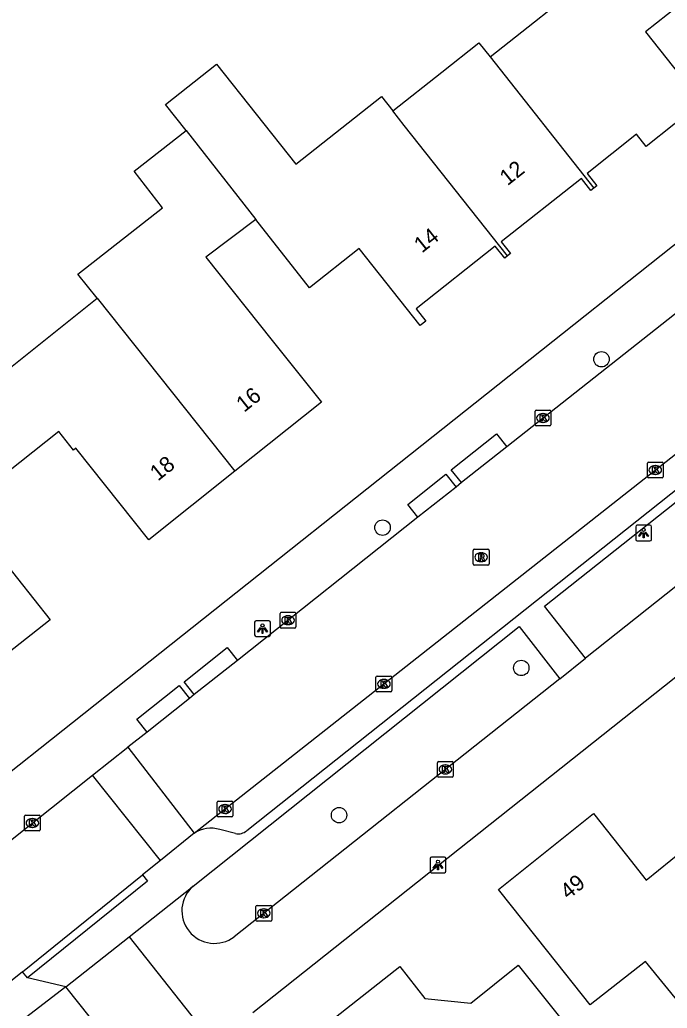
# Model space of a CAD drawing. Extents: x 159503 to 160347, y 382525 to 383272.
# Drawn here: x 159954.6 to 159995.6, y 383112.7 to 383175.2 of the extents above; entities that cross this region are included whole.
import ezdxf

# ---------------------------------------------------------------- set-up
doc = ezdxf.new("R2010")
doc.units = 0
for name, color, linetype in [('IMGEO_Boom', 7, 'Continuous'), ('IMGEO_Kolk', 7, 'Continuous'), ('IMGEO_Lichtpunt', 7, 'Continuous'), ('IMGEO_Pand', 7, 'Continuous'), ('IMGEO_Pand_nummerreeks', 7, 'Continuous'), ('IMGEO_Rijbaan_lokaal_open', 7, 'Continuous'), ('IMGEO_Rioolput', 7, 'Continuous'), ('IMGEO_Voetpad_open', 7, 'Continuous')]:
    doc.layers.add(name, color=color, linetype=linetype)

msp = doc.modelspace()

# ---------------------------------------------------------------- linework, layer by layer
at = {"layer": 'IMGEO_Boom'}
for centre in [(159991.403, 383153.748), (159977.549, 383143.088), (159986.328, 383134.208), (159974.796, 383124.886)]:
    msp.add_circle(centre, 0.489, dxfattribs=at)
at = {"layer": 'IMGEO_Kolk'}
for p, q in [((159987.201, 383149.604), (159987.201, 383150.456)), ((159987.276, 383150.53), (159988.128, 383150.53)), ((159987.689, 383150.31), (159987.714, 383150.31)), ((159988.202, 383150.456), (159988.202, 383149.604)), ((159988.128, 383149.53), (159987.276, 383149.53)), ((159987.712, 383149.75), (159987.687, 383149.75)), ((159994.308, 383146.308), (159994.308, 383147.16)), ((159994.383, 383147.234), (159995.235, 383147.234)), ((159994.796, 383147.014), (159994.821, 383147.014)), ((159995.309, 383147.16), (159995.309, 383146.308)), ((159994.819, 383146.454), (159994.794, 383146.454)), ((159995.235, 383146.234), (159994.383, 383146.234)), ((159971.064, 383136.801), (159971.064, 383137.653)), ((159971.139, 383137.727), (159971.991, 383137.727)), ((159972.065, 383137.653), (159972.065, 383136.801)), ((159971.552, 383137.507), (159971.577, 383137.507)), ((159971.991, 383136.727), (159971.139, 383136.727)), ((159971.575, 383136.947), (159971.55, 383136.947)), ((159977.131, 383132.77), (159977.131, 383133.622)), ((159977.206, 383133.696), (159978.058, 383133.696)), ((159977.619, 383133.476), (159977.644, 383133.476)), ((159978.132, 383133.622), (159978.132, 383132.77)), ((159978.058, 383132.696), (159977.206, 383132.696)), ((159977.642, 383132.916), (159977.617, 383132.916)), ((159981.097, 383128.283), (159981.949, 383128.283)), ((159981.022, 383127.357), (159981.022, 383128.209)), ((159981.51, 383128.063), (159981.535, 383128.063)), ((159982.023, 383128.209), (159982.023, 383127.357)), ((159981.949, 383127.283), (159981.097, 383127.283)), ((159981.533, 383127.503), (159981.508, 383127.503)), ((159967.153, 383125.773), (159968.005, 383125.773)), ((159967.078, 383124.847), (159967.078, 383125.699)), ((159967.566, 383125.553), (159967.591, 383125.553)), ((159968.079, 383125.699), (159968.079, 383124.847)), ((159954.884, 383123.961), (159954.884, 383124.813)), ((159954.959, 383124.887), (159955.811, 383124.887)), ((159955.372, 383124.667), (159955.397, 383124.667)), ((159955.885, 383124.813), (159955.885, 383123.961)), ((159968.005, 383124.773), (159967.153, 383124.773)), ((159967.589, 383124.993), (159967.564, 383124.993)), ((159955.811, 383123.887), (159954.959, 383123.887)), ((159955.395, 383124.107), (159955.37, 383124.107)), ((159969.532, 383118.248), (159969.532, 383119.1)), ((159969.607, 383119.174), (159970.459, 383119.174)), ((159970.02, 383118.954), (159970.045, 383118.954)), ((159970.533, 383119.1), (159970.533, 383118.248)), ((159970.043, 383118.394), (159970.018, 383118.394)), ((159970.459, 383118.174), (159969.607, 383118.174))]:
    msp.add_line(p, q, dxfattribs=at)
for points in [[(159987.201, 383149.604), (159987.201, 383150.456)], [(159987.276, 383150.53), (159988.128, 383150.53)], [(159987.522, 383150.23), (159987.645, 383150.23), (159987.645, 383150.079), (159987.775, 383150.23), (159987.939, 383150.23), (159987.793, 383150.079), (159987.946, 383149.83), (159987.794, 383149.83), (159987.709, 383149.994), (159987.645, 383149.927), (159987.645, 383149.83), (159987.522, 383149.83), (159987.522, 383150.23)], [(159988.202, 383150.456), (159988.202, 383149.604)], [(159988.128, 383149.53), (159987.276, 383149.53)], [(159994.308, 383146.308), (159994.308, 383147.16)], [(159994.383, 383147.234), (159995.235, 383147.234)], [(159995.309, 383147.16), (159995.309, 383146.308)], [(159994.629, 383146.934), (159994.752, 383146.934), (159994.752, 383146.783), (159994.882, 383146.934), (159995.046, 383146.934), (159994.9, 383146.783), (159995.053, 383146.534), (159994.901, 383146.534), (159994.816, 383146.698), (159994.752, 383146.631), (159994.752, 383146.534), (159994.629, 383146.534), (159994.629, 383146.934)], [(159995.235, 383146.234), (159994.383, 383146.234)], [(159971.064, 383136.801), (159971.064, 383137.653)], [(159971.139, 383137.727), (159971.991, 383137.727)], [(159972.065, 383137.653), (159972.065, 383136.801)], [(159971.385, 383137.427), (159971.508, 383137.427), (159971.508, 383137.276), (159971.638, 383137.427), (159971.802, 383137.427), (159971.656, 383137.276), (159971.809, 383137.027), (159971.657, 383137.027), (159971.572, 383137.191), (159971.508, 383137.124), (159971.508, 383137.027), (159971.385, 383137.027), (159971.385, 383137.427)], [(159971.991, 383136.727), (159971.139, 383136.727)], [(159977.131, 383132.77), (159977.131, 383133.622)], [(159977.206, 383133.696), (159978.058, 383133.696)], [(159977.452, 383133.396), (159977.575, 383133.396), (159977.575, 383133.245), (159977.705, 383133.396), (159977.869, 383133.396), (159977.723, 383133.245), (159977.876, 383132.996), (159977.724, 383132.996), (159977.639, 383133.16), (159977.575, 383133.093), (159977.575, 383132.996), (159977.452, 383132.996), (159977.452, 383133.396)], [(159978.132, 383133.622), (159978.132, 383132.77)], [(159978.058, 383132.696), (159977.206, 383132.696)], [(159981.097, 383128.283), (159981.949, 383128.283)], [(159981.022, 383127.357), (159981.022, 383128.209)], [(159981.343, 383127.983), (159981.466, 383127.983), (159981.466, 383127.832), (159981.596, 383127.983), (159981.76, 383127.983), (159981.614, 383127.832), (159981.767, 383127.583), (159981.615, 383127.583), (159981.53, 383127.747), (159981.466, 383127.68), (159981.466, 383127.583), (159981.343, 383127.583), (159981.343, 383127.983)], [(159982.023, 383128.209), (159982.023, 383127.357)], [(159981.949, 383127.283), (159981.097, 383127.283)], [(159967.153, 383125.773), (159968.005, 383125.773)], [(159967.078, 383124.847), (159967.078, 383125.699)], [(159967.399, 383125.473), (159967.522, 383125.473), (159967.522, 383125.322), (159967.652, 383125.473), (159967.816, 383125.473), (159967.67, 383125.322), (159967.823, 383125.073), (159967.671, 383125.073), (159967.586, 383125.237), (159967.522, 383125.17), (159967.522, 383125.073), (159967.399, 383125.073), (159967.399, 383125.473)], [(159968.079, 383125.699), (159968.079, 383124.847)], [(159954.884, 383123.961), (159954.884, 383124.813)], [(159954.959, 383124.887), (159955.811, 383124.887)], [(159955.205, 383124.587), (159955.328, 383124.587), (159955.328, 383124.436), (159955.458, 383124.587), (159955.622, 383124.587), (159955.476, 383124.436), (159955.629, 383124.187), (159955.477, 383124.187), (159955.392, 383124.351), (159955.328, 383124.284), (159955.328, 383124.187), (159955.205, 383124.187), (159955.205, 383124.587)], [(159955.885, 383124.813), (159955.885, 383123.961)], [(159968.005, 383124.773), (159967.153, 383124.773)], [(159955.811, 383123.887), (159954.959, 383123.887)], [(159969.532, 383118.248), (159969.532, 383119.1)], [(159969.607, 383119.174), (159970.459, 383119.174)], [(159969.853, 383118.874), (159969.976, 383118.874), (159969.976, 383118.723), (159970.106, 383118.874), (159970.27, 383118.874), (159970.124, 383118.723), (159970.277, 383118.474), (159970.125, 383118.474), (159970.04, 383118.638), (159969.976, 383118.571), (159969.976, 383118.474), (159969.853, 383118.474), (159969.853, 383118.874)], [(159970.533, 383119.1), (159970.533, 383118.248)], [(159970.459, 383118.174), (159969.607, 383118.174)]]:
    msp.add_lwpolyline(points, dxfattribs=at)
for centre, start, end in [((159987.278, 383150.454), 91.55205, 178.44795), ((159987.278, 383150.454), 91.55205, 178.44795), ((159988.126, 383150.454), 1.55205, 88.44795), ((159988.126, 383150.454), 1.55205, 88.44795), ((159987.278, 383149.606), 181.55205, 268.44795), ((159987.278, 383149.606), 181.55205, 268.44795), ((159988.126, 383149.606), 271.55205, 358.44795), ((159988.126, 383149.606), 271.55205, 358.44795), ((159994.385, 383147.158), 91.55205, 178.44795), ((159994.385, 383147.158), 91.55205, 178.44795), ((159995.233, 383147.158), 1.55205, 88.44795), ((159995.233, 383147.158), 1.55205, 88.44795), ((159994.385, 383146.31), 181.55205, 268.44795), ((159994.385, 383146.31), 181.55205, 268.44795), ((159995.233, 383146.31), 271.55205, 358.44795), ((159995.233, 383146.31), 271.55205, 358.44795), ((159971.141, 383137.651), 91.55205, 178.44795), ((159971.141, 383137.651), 91.55205, 178.44795), ((159971.989, 383137.651), 1.55205, 88.44795), ((159971.989, 383137.651), 1.55205, 88.44795), ((159971.141, 383136.803), 181.55205, 268.44795), ((159971.141, 383136.803), 181.55205, 268.44795), ((159971.989, 383136.803), 271.55205, 358.44795), ((159971.989, 383136.803), 271.55205, 358.44795), ((159977.208, 383133.62), 91.55205, 178.44795), ((159977.208, 383133.62), 91.55205, 178.44795), ((159978.056, 383133.62), 1.55205, 88.44795), ((159978.056, 383133.62), 1.55205, 88.44795), ((159977.208, 383132.772), 181.55205, 268.44795), ((159977.208, 383132.772), 181.55205, 268.44795), ((159978.056, 383132.772), 271.55205, 358.44795), ((159978.056, 383132.772), 271.55205, 358.44795), ((159981.099, 383128.207), 91.55205, 178.44795), ((159981.099, 383128.207), 91.55205, 178.44795), ((159981.947, 383128.207), 1.55205, 88.44795), ((159981.947, 383128.207), 1.55205, 88.44795), ((159981.099, 383127.359), 181.55205, 268.44795), ((159981.099, 383127.359), 181.55205, 268.44795), ((159981.947, 383127.359), 271.55205, 358.44795), ((159981.947, 383127.359), 271.55205, 358.44795), ((159967.155, 383125.697), 91.55205, 178.44795), ((159967.155, 383125.697), 91.55205, 178.44795), ((159968.003, 383125.697), 1.55205, 88.44795), ((159968.003, 383125.697), 1.55205, 88.44795), ((159954.961, 383124.811), 91.55205, 178.44795), ((159954.961, 383124.811), 91.55205, 178.44795), ((159955.809, 383124.811), 1.55205, 88.44795), ((159955.809, 383124.811), 1.55205, 88.44795), ((159967.155, 383124.849), 181.55205, 268.44795), ((159967.155, 383124.849), 181.55205, 268.44795), ((159968.003, 383124.849), 271.55205, 358.44795), ((159968.003, 383124.849), 271.55205, 358.44795), ((159954.961, 383123.963), 181.55205, 268.44795), ((159954.961, 383123.963), 181.55205, 268.44795), ((159955.809, 383123.963), 271.55205, 358.44795), ((159955.809, 383123.963), 271.55205, 358.44795), ((159969.609, 383119.098), 91.55205, 178.44795), ((159969.609, 383119.098), 91.55205, 178.44795), ((159970.457, 383119.098), 1.55205, 88.44795), ((159970.457, 383119.098), 1.55205, 88.44795), ((159969.609, 383118.25), 181.55205, 268.44795), ((159969.609, 383118.25), 181.55205, 268.44795), ((159970.457, 383118.25), 271.55205, 358.44795), ((159970.457, 383118.25), 271.55205, 358.44795)]:
    msp.add_arc(centre, 0.0765, start, end, dxfattribs=at)
for centre, major_axis, ratio, start_param, end_param in [((159987.688, 383150.03), (-0.387, 0.002), 0.722429, 4.712389, 7.853982), ((159987.713, 383150.03), (-0.39, 0.002), 0.717154, 1.570796, 4.712389), ((159994.795, 383146.734), (-0.387, 0.002), 0.722429, 4.712389, 7.853982), ((159994.82, 383146.734), (-0.39, 0.002), 0.717154, 1.570796, 4.712389), ((159971.551, 383137.227), (-0.387, 0.002), 0.722429, 4.712389, 7.853982), ((159971.576, 383137.227), (-0.39, 0.002), 0.717154, 1.570796, 4.712389), ((159977.618, 383133.196), (-0.387, 0.002), 0.722429, 4.712389, 7.853982), ((159977.643, 383133.196), (-0.39, 0.002), 0.717154, 1.570796, 4.712389), ((159981.509, 383127.783), (-0.387, 0.002), 0.722429, 4.712389, 7.853982), ((159981.534, 383127.783), (-0.39, 0.002), 0.717154, 1.570796, 4.712389), ((159967.565, 383125.273), (-0.387, 0.002), 0.722429, 4.712389, 7.853982), ((159967.59, 383125.273), (-0.39, 0.002), 0.717154, 1.570796, 4.712389), ((159955.371, 383124.387), (-0.387, 0.002), 0.722429, 4.712389, 7.853982), ((159955.396, 383124.387), (-0.39, 0.002), 0.717154, 1.570796, 4.712389), ((159970.019, 383118.674), (-0.387, 0.002), 0.722429, 4.712389, 7.853982), ((159970.044, 383118.674), (-0.39, 0.002), 0.717154, 1.570796, 4.712389)]:
    msp.add_ellipse(centre, major_axis=major_axis, ratio=ratio, start_param=start_param, end_param=end_param, dxfattribs=at)
at = {"layer": 'IMGEO_Lichtpunt'}
for p, q in [((159993.573, 383143.149), (159993.573, 383142.342)), ((159993.573, 383143.149), (159993.573, 383142.342)), ((159994.475, 383143.244), (159993.667, 383143.244)), ((159994.475, 383143.244), (159993.667, 383143.244)), ((159994.569, 383142.342), (159994.569, 383143.149)), ((159994.569, 383142.342), (159994.569, 383143.149)), ((159993.667, 383142.248), (159994.475, 383142.248)), ((159993.667, 383142.248), (159994.475, 383142.248)), ((159969.452, 383137.103), (159969.452, 383136.296)), ((159969.452, 383137.103), (159969.452, 383136.296)), ((159970.354, 383137.198), (159969.546, 383137.198)), ((159970.354, 383137.198), (159969.546, 383137.198)), ((159970.448, 383136.296), (159970.448, 383137.103)), ((159970.448, 383136.296), (159970.448, 383137.103)), ((159969.546, 383136.202), (159970.354, 383136.202)), ((159969.546, 383136.202), (159970.354, 383136.202)), ((159980.557, 383122.142), (159980.557, 383121.335)), ((159980.557, 383122.142), (159980.557, 383121.335)), ((159981.459, 383122.237), (159980.651, 383122.237)), ((159981.459, 383122.237), (159980.651, 383122.237)), ((159981.553, 383121.335), (159981.553, 383122.142)), ((159981.553, 383121.335), (159981.553, 383122.142)), ((159980.651, 383121.241), (159981.459, 383121.241)), ((159980.651, 383121.241), (159981.459, 383121.241))]:
    msp.add_line(p, q, dxfattribs=at)
for points in [[(159993.947, 383142.813), (159993.986, 383142.785), (159993.798, 383142.523), (159993.76, 383142.55), (159993.947, 383142.813)], [(159994.049, 383142.765), (159994.096, 383142.765), (159994.096, 383142.443), (159994.049, 383142.443), (159994.049, 383142.765)], [(159994.159, 383142.785), (159994.197, 383142.812), (159994.384, 383142.55), (159994.345, 383142.522), (159994.159, 383142.785)], [(159969.826, 383136.767), (159969.865, 383136.739), (159969.677, 383136.477), (159969.639, 383136.504), (159969.826, 383136.767)], [(159969.928, 383136.719), (159969.975, 383136.719), (159969.975, 383136.397), (159969.928, 383136.397), (159969.928, 383136.719)], [(159970.038, 383136.739), (159970.076, 383136.766), (159970.263, 383136.504), (159970.224, 383136.476), (159970.038, 383136.739)], [(159980.931, 383121.806), (159980.97, 383121.778), (159980.782, 383121.516), (159980.744, 383121.543), (159980.931, 383121.806)], [(159981.033, 383121.758), (159981.08, 383121.758), (159981.08, 383121.436), (159981.033, 383121.436), (159981.033, 383121.758)], [(159981.143, 383121.778), (159981.181, 383121.805), (159981.368, 383121.543), (159981.329, 383121.515), (159981.143, 383121.778)]]:
    msp.add_lwpolyline(points, dxfattribs=at)
for centre in [(159994.072, 383142.947), (159969.951, 383136.901), (159981.056, 383121.94)]:
    msp.add_circle(centre, 0.0994, dxfattribs=at)
for centre, start, end in [((159993.667, 383143.149), 90, 180), ((159993.667, 383143.149), 90, 180), ((159994.475, 383143.149), 0, 90), ((159994.475, 383143.149), 0, 90), ((159993.667, 383142.342), 180, 270), ((159993.667, 383142.342), 180, 270), ((159994.475, 383142.342), 270, 0), ((159994.475, 383142.342), 270, 360), ((159969.546, 383137.103), 90, 180), ((159969.546, 383137.103), 90, 180), ((159970.354, 383137.103), 0, 90), ((159970.354, 383137.103), 0, 90), ((159969.546, 383136.296), 180, 270), ((159969.546, 383136.296), 180, 270), ((159970.354, 383136.296), 270, 0), ((159970.354, 383136.296), 270, 360), ((159980.651, 383122.142), 90, 180), ((159980.651, 383122.142), 90, 180), ((159981.459, 383122.142), 0, 90), ((159981.459, 383122.142), 0, 90), ((159980.651, 383121.335), 180, 270), ((159980.651, 383121.335), 180, 270), ((159981.459, 383121.335), 270, 0), ((159981.459, 383121.335), 270, 360)]:
    msp.add_arc(centre, 0.0946, start, end, dxfattribs=at)
at = {"layer": 'IMGEO_Pand'}
for points in [[(159984.351, 383172.885), (159990.881, 383178.054), (159988.215, 383181.422), (159986.562, 383188.124), (159988.86, 383188.691), (159993.714, 383189.888), (159996.968, 383176.687), (159994.184, 383174.484), (159997.738, 383169.994), (159994.233, 383167.22), (159993.625, 383167.988), (159990.5, 383165.513), (159991.114, 383164.737), (159990.923, 383164.586)], [(159978.198, 383169.471), (159981.303, 383171.93), (159983.636, 383173.777), (159984.351, 383172.885)], [(159984.351, 383172.885), (159990.923, 383164.586)], [(159965.112, 383168.222), (159963.819, 383169.871), (159967.029, 383172.422), (159972.052, 383166.099), (159977.473, 383170.391), (159978.198, 383169.471)], [(159985.462, 383160.294), (159978.922, 383168.551), (159978.198, 383169.471)], [(159959.487, 383157.608), (159958.267, 383159.133), (159963.63, 383163.326), (159961.817, 383165.646), (159965.112, 383168.222)], [(159965.112, 383168.222), (159969.521, 383162.599)], [(159990.923, 383164.586), (159990.733, 383164.436), (159990.138, 383165.188), (159985.064, 383161.172), (159985.645, 383160.439), (159985.462, 383160.294)], [(159969.521, 383162.599), (159966.366, 383160.212), (159970.559, 383154.936), (159973.675, 383151.025), (159968.19, 383146.654)], [(159985.462, 383160.294), (159985.28, 383160.15), (159984.685, 383160.902), (159979.672, 383156.934), (159980.279, 383156.167), (159979.932, 383155.892), (159976.071, 383160.769), (159972.927, 383158.28), (159969.521, 383162.599)], [(159944.335, 383158.41), (159947.715, 383161.103), (159953.991, 383153.228), (159959.487, 383157.608)], [(159959.487, 383157.608), (159968.19, 383146.654)], [(159968.19, 383146.654), (159962.752, 383142.321), (159958.134, 383148.116), (159957.986, 383147.998), (159957.052, 383149.172), (159953.776, 383146.561), (159949.956, 383151.355)], [(159944.875, 383140.308), (159948.168, 383142.91), (159946.696, 383144.773), (159949.077, 383146.654), (159950.584, 383144.744), (159953.402, 383141.175), (159956.502, 383137.251), (159951.497, 383133.297), (159951.868, 383132.826), (159951.175, 383132.278)], [(160002.296, 383117.538), (160002.349, 383117.471), (160000, 383115.631), (159996.451, 383112.851), (159994.2, 383115.629), (159990.696, 383112.874), (159987.999, 383116.264), (159984.887, 383120.176), (159990.894, 383124.991), (159992.99, 383122.344), (159994.232, 383120.776), (159997.365, 383123.295), (159996.151, 383124.828), (159996.416, 383125.034), (159998.829, 383121.957)], [(159990.718, 383109.639), (159985.126, 383105.184), (159985.737, 383104.418), (159986.361, 383104.917), (159987.389, 383103.626), (159986.881, 383103.221), (159982.971, 383100.104), (159980.091, 383103.717), (159980.599, 383104.122), (159978.131, 383107.219), (159977.63, 383106.82), (159973.87, 383111.54), (159978.65, 383115.3), (159980.233, 383113.288), (159983.128, 383112.99), (159986.139, 383115.388), (159989.255, 383111.477), (159990.718, 383109.639)]]:
    msp.add_lwpolyline(points, dxfattribs=at)
at = {"layer": 'IMGEO_Rijbaan_lokaal_open'}
for points in [[(160007.337, 383165.518), (159985.41, 383148.209)], [(159965.635, 383123.738), (160005.521, 383155.177)], [(159985.41, 383148.209), (159982.548, 383145.937)], [(159982.548, 383145.937), (159982.197, 383145.658)], [(159982.197, 383145.658), (159979.79, 383143.748)], [(159979.79, 383143.748), (159968.366, 383134.687)], [(160000, 383142.448), (159990.398, 383134.835)], [(160001.274, 383140.9), (160002.826, 383138.938), (160000, 383136.696), (159969.339, 383112.369)], [(159968.366, 383134.687), (159965.633, 383132.52)], [(159988.759, 383133.521), (159990.398, 383134.835)], [(159988.759, 383133.521), (159968.16, 383117.19)], [(159965.323, 383132.274), (159962.64, 383130.146)], [(159965.633, 383132.52), (159965.323, 383132.274)], [(159962.64, 383130.146), (159961.424, 383129.181)], [(159959.2, 383127.414), (159961.424, 383129.181)], [(159961.424, 383129.181), (159965.635, 383123.738)], [(159950.655, 383120.624), (159951.49, 383121.291), (159959.2, 383127.414)], [(159963.491, 383122.013), (159959.2, 383127.414)], [(159965.635, 383123.738), (159963.491, 383122.013)], [(159963.491, 383122.013), (159962.358, 383121.1)], [(159954.759, 383114.972), (159962.358, 383121.1)], [(159961.505, 383117.191), (159965.56, 383120.401)], [(159957.5, 383114.019), (159961.505, 383117.191)], [(159961.505, 383117.191), (159966.858, 383110.439)], [(159954.759, 383114.972), (159950.297, 383111.374)], [(159957.5, 383114.019), (159954.685, 383111.851)], [(159962.836, 383107.311), (159957.5, 383114.019)]]:
    msp.add_lwpolyline(points, dxfattribs=at)
msp.add_arc((159966.913, 383118.839), 2.067, 130.89214, 307.10319, dxfattribs=at)
at = {"layer": 'IMGEO_Rioolput'}
for p, q in [((159983.288, 383140.79), (159983.288, 383141.642)), ((159983.363, 383141.716), (159984.215, 383141.716)), ((159983.776, 383141.496), (159983.801, 383141.496)), ((159984.289, 383141.642), (159984.289, 383140.79)), ((159983.799, 383140.936), (159983.774, 383140.936)), ((159984.215, 383140.716), (159983.363, 383140.716))]:
    msp.add_line(p, q, dxfattribs=at)
for points in [[(159983.288, 383140.79), (159983.288, 383141.642)], [(159983.363, 383141.716), (159984.215, 383141.716)], [(159983.877, 383141.414), (159983.625, 383141.416), (159983.625, 383141.016)], [(159984.289, 383141.642), (159984.289, 383140.79)], [(159983.625, 383141.016), (159983.749, 383141.016), (159983.749, 383141.178), (159983.76, 383141.178)], [(159983.803, 383141.335), (159983.749, 383141.335), (159983.749, 383141.254)], [(159983.749, 383141.254), (159983.801, 383141.254)], [(159983.807, 383141.149), (159983.878, 383141.016), (159984.018, 383141.016), (159983.953, 383141.142)], [(159984.215, 383140.716), (159983.363, 383140.716)]]:
    msp.add_lwpolyline(points, dxfattribs=at)
for centre, radius, start, end in [((159983.365, 383141.64), 0.0765, 91.55205, 178.44795), ((159983.365, 383141.64), 0.0765, 91.55205, 178.44795), ((159983.876, 383141.304), 0.109, 350.36119, 89.41601), ((159984.213, 383141.64), 0.0765, 1.55205, 88.44795), ((159984.213, 383141.64), 0.0765, 1.55205, 88.44795), ((159983.365, 383140.792), 0.0765, 181.55205, 268.44795), ((159983.365, 383140.792), 0.0765, 181.55205, 268.44795), ((159983.759, 383141.125), 0.0533, 26.02933, 88.69889), ((159983.785, 383141.443), 0.19, 274.7715, 282.96867), ((159983.809, 383141.239), 0.0964, 77.00612, 93.18647), ((159983.823, 383141.296), 0.0378, 276.66336, 79.67722), ((159983.874, 383141.304), 0.112, 277.58423, 350.98172), ((159983.858, 383141.089), 0.108, 29.51342, 73.79051), ((159984.213, 383140.792), 0.0765, 271.55205, 358.44795), ((159984.213, 383140.792), 0.0765, 271.55205, 358.44795)]:
    msp.add_arc(centre, radius, start, end, dxfattribs=at)
for centre, major_axis, ratio, start_param, end_param in [((159983.775, 383141.216), (-0.387, 0.002), 0.722429, 4.712389, 7.853982), ((159983.8, 383141.216), (-0.39, 0.002), 0.717154, 1.570796, 4.712389)]:
    msp.add_ellipse(centre, major_axis=major_axis, ratio=ratio, start_param=start_param, end_param=end_param, dxfattribs=at)
at = {"layer": 'IMGEO_Voetpad_open'}
for points in [[(159838.776, 383036.162), (160000, 383164.155), (160003.86, 383167.245)], [(159990.398, 383134.835), (159987.796, 383138.118), (160000, 383147.78), (160009.287, 383155.131)], [(160004.48, 383152.096), (160000, 383148.54), (159968.962, 383123.902)], [(159982.548, 383145.937), (159981.901, 383146.752), (159984.763, 383149.024), (159985.41, 383148.209)], [(159979.79, 383143.748), (159979.144, 383144.563), (159981.551, 383146.473), (159982.197, 383145.658)], [(159965.56, 383120.401), (159986.191, 383136.82), (159988.759, 383133.521)], [(159965.633, 383132.52), (159964.987, 383133.335), (159967.72, 383135.502), (159968.366, 383134.687)], [(159962.64, 383130.146), (159961.994, 383130.961), (159964.677, 383133.089), (159965.323, 383132.274)], [(159968.239, 383123.717), (159967.244, 383123.978)], [(159962.358, 383121.1), (159962.671, 383120.711), (159955.072, 383114.583)], [(159955.072, 383114.583), (159954.759, 383114.972)], [(159957.5, 383114.019), (159955.072, 383114.583)]]:
    msp.add_lwpolyline(points, dxfattribs=at)
for centre, radius, start, end in [((159966.693, 383122.161), 1.898, 73.11474, 123.85275), ((159968.4, 383124.591), 0.889, 259.53557, 309.17001)]:
    msp.add_arc(centre, radius, start, end, dxfattribs=at)

# ---------------------------------------------------------------- texts
at = {"layer": 'IMGEO_Pand_nummerreeks'}
for s, rotation, p in [('12', 38.35952, (159985.458, 383164.698)), ('14', 38.36525, (159980.038, 383160.437)), ('16', 38.5486, (159968.787, 383150.352)), ('18', 38.54785, (159963.328, 383146.002)), ('49', 38.71476, (159989.298, 383119.508))]:
    msp.add_text(s, height=1, rotation=rotation, dxfattribs=at).set_placement(p)

doc.saveas('drawing.dxf')
